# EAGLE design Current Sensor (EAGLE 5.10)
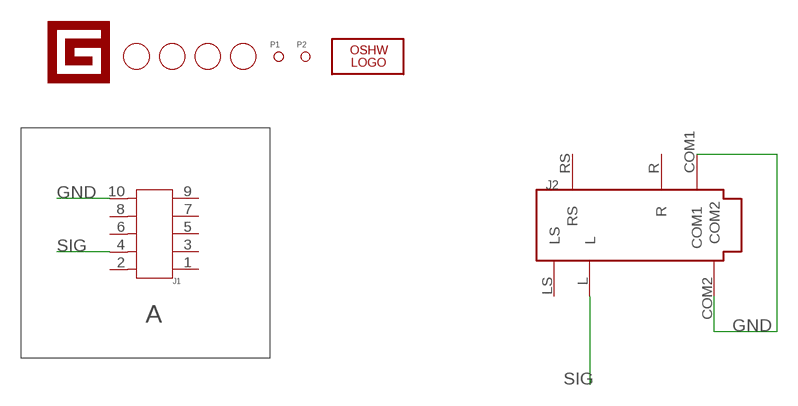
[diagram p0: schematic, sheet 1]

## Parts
J1  HEADER-SHF-105-01-L-D-SM  [SHF-105-01-L-D-SM]
J2  AUDIO-SMT  [3.5-SMD]
LOGO1  LOGO-OSHW-FILLX0150-NT  [OSHW_FILLX150_NOTEXT]
P1  PAD-MARK  [ROUND-MARK-0.635]
P2  PAD-MARK  [ROUND-MARK-0.635]
U$1  LOGO-GADGETEER-NORMAL  [GADGETEER-SILK]
U$2  PAD-HOLE'3.2/7.0'  [HOLE-D-3.2/7.0]
U$3  PAD-HOLE'3.2/7.0'  [HOLE-D-3.2/7.0]
U$4  PAD-HOLE'3.2/7.0'  [HOLE-D-3.2/7.0]
U$5  PAD-HOLE'3.2/7.0'  [HOLE-D-3.2/7.0]

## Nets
GND: J1.10 J2.COM1 J2.COM2
SIG: J1.4 J2.L
Unconnected: J1.1 J1.2 J1.3 J1.5 J1.6 J1.7 J1.8 J1.9 J2.LS J2.R J2.RS

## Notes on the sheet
- A

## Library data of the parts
J1 = Connector:HEADER-SHF-105-01-L-D-SM
J2 = Connector:AUDIO-SMT
LOGO1 = Logo:LOGO-OSHW-FILL
P1 P2 = Discreter:PAD-MARK
U$1 = Logo:LOGO-GADGETEER
U$2-U$5 = Discreter:PAD-HOLE

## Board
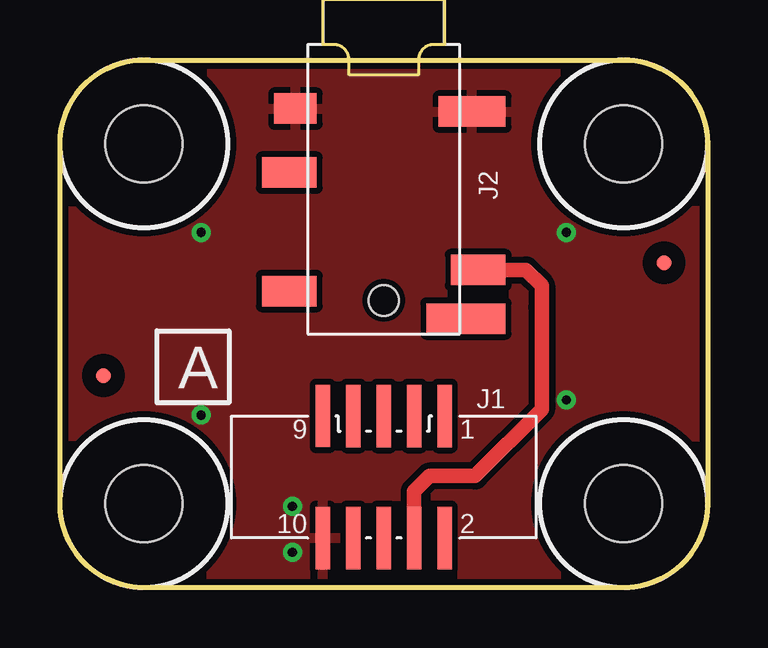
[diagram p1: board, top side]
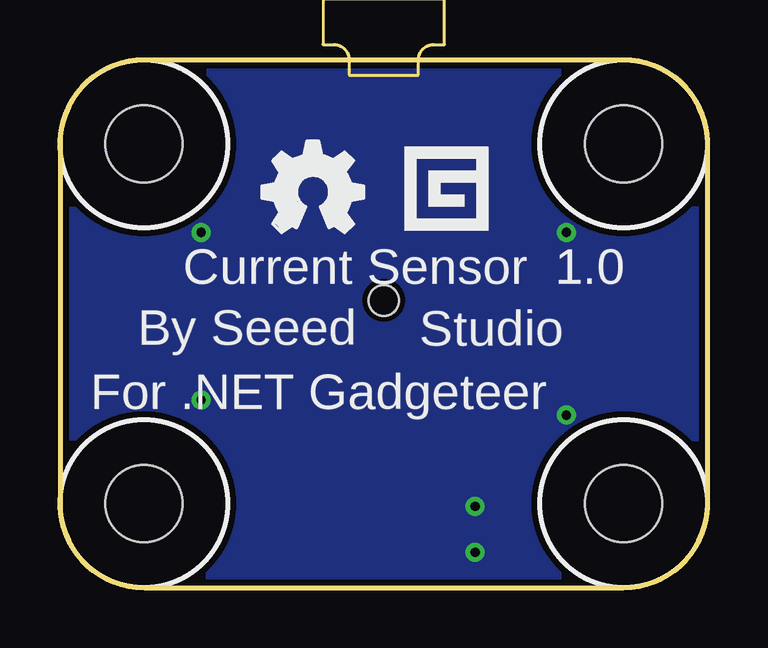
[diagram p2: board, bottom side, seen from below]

Size 27 x 22 mm. Coordinates in mm from the lower left corner, seen from the top.
Outline: 0,18.5 arc-90 3.5,22 23.5,22 arc-90 27,18.5 27,3.5 arc-90 23.5,0 3.5,0 arc-90 0,3.5 0,18.5
Copper layers (1*16): Top 0.035mm / dielectric 1.5mm / Bottom 0.035mm
Design rules "default *": minimum track width 10mil, minimum drill 12mil, track to track 8mil, track to pad 8mil, pad to pad 8mil, via to via 8mil, smd to smd 8mil, copper to edge 10mil, drill to drill 8mil, minimum pad ring 10mil, minimum via ring 8mil, stop-mask expansion 4mil, vias tented up to drill 25mil, thermal gap 10mil

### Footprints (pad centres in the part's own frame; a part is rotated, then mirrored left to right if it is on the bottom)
SHF-105-01-L-D-SM = smd 0.6 x 2.6: 1 -2.54,-2.54; 2 -2.54,2.54; 3 -1.27,-2.54; 4 -1.27,2.54; 5 0,-2.54; 6 0,2.54; 7 1.27,-2.54; 8 1.27,2.54; 9 2.54,-2.546; 10 2.54,2.54
3.5-SMD = smd 1.27 x 1.778: COM1 -4.572,3.683 | smd 1.27 x 2.794: COM2 -4.699,-3.683 | smd 1.27 x 2.286: L -11.303,-3.937; R -7.239,3.937; RS -12.192,3.937 | smd 1.27 x 3.302: LS -13.335,-3.429 | hole 1.27: -12.573,0
ROUND-MARK-0.635 = smd 0.635 x 0.635: P$1 0,0
HOLE-D-3.2/7.0 = hole 3.2: 0,0

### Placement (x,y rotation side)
J1  13.5,4.61 180 top
J2  13.5,24.55 90 top
LOGO1  18.58,14.81 0 bottom
P1  25.18,13.54 270 top
P2  1.82,8.84 270 top
U$1  10.47,17.07 0 bottom
U$2  23.5,18.5 270 top
U$3  3.5,18.5 0 top
U$4  23.5,3.5 270 top
U$5  3.5,3.5 0 top

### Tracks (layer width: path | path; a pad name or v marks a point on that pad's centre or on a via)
GND  (via drill 0.38)
  other vias: 21.12,14.81 5.88,14.81 21.12,7.83 5.88,7.19 9.69,3.38 9.69,1.47
  pour Top (isolate 0.254): 30.01,23.02 30.01,-2.34 -3.01,-2.34 -3.01,23.02
  pour Bottom (isolate 0.254): 30.01,23.02 30.01,-2.34 -3.01,-2.34 -3.01,23.02
SIG
  Top 0.61: J1.4 14.77,4.01 15.4,4.65 17.31,4.65 20.09,7.43 20.09,11.69 20.09,12.59 19.43,13.25 J2.L

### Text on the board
tPlace: A
bPlace: 1.0 | Current Sensor | By Seeed | Studio | For .NET Gadgeteer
